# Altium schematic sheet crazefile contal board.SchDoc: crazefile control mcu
size A4; CompanyName: 良工作室; DrawnBy: 郑良杰; Engineer: 郑良杰; Organization: 良工作室; DocumentNumber: 1; SheetNumber: 1; SheetTotal: 4
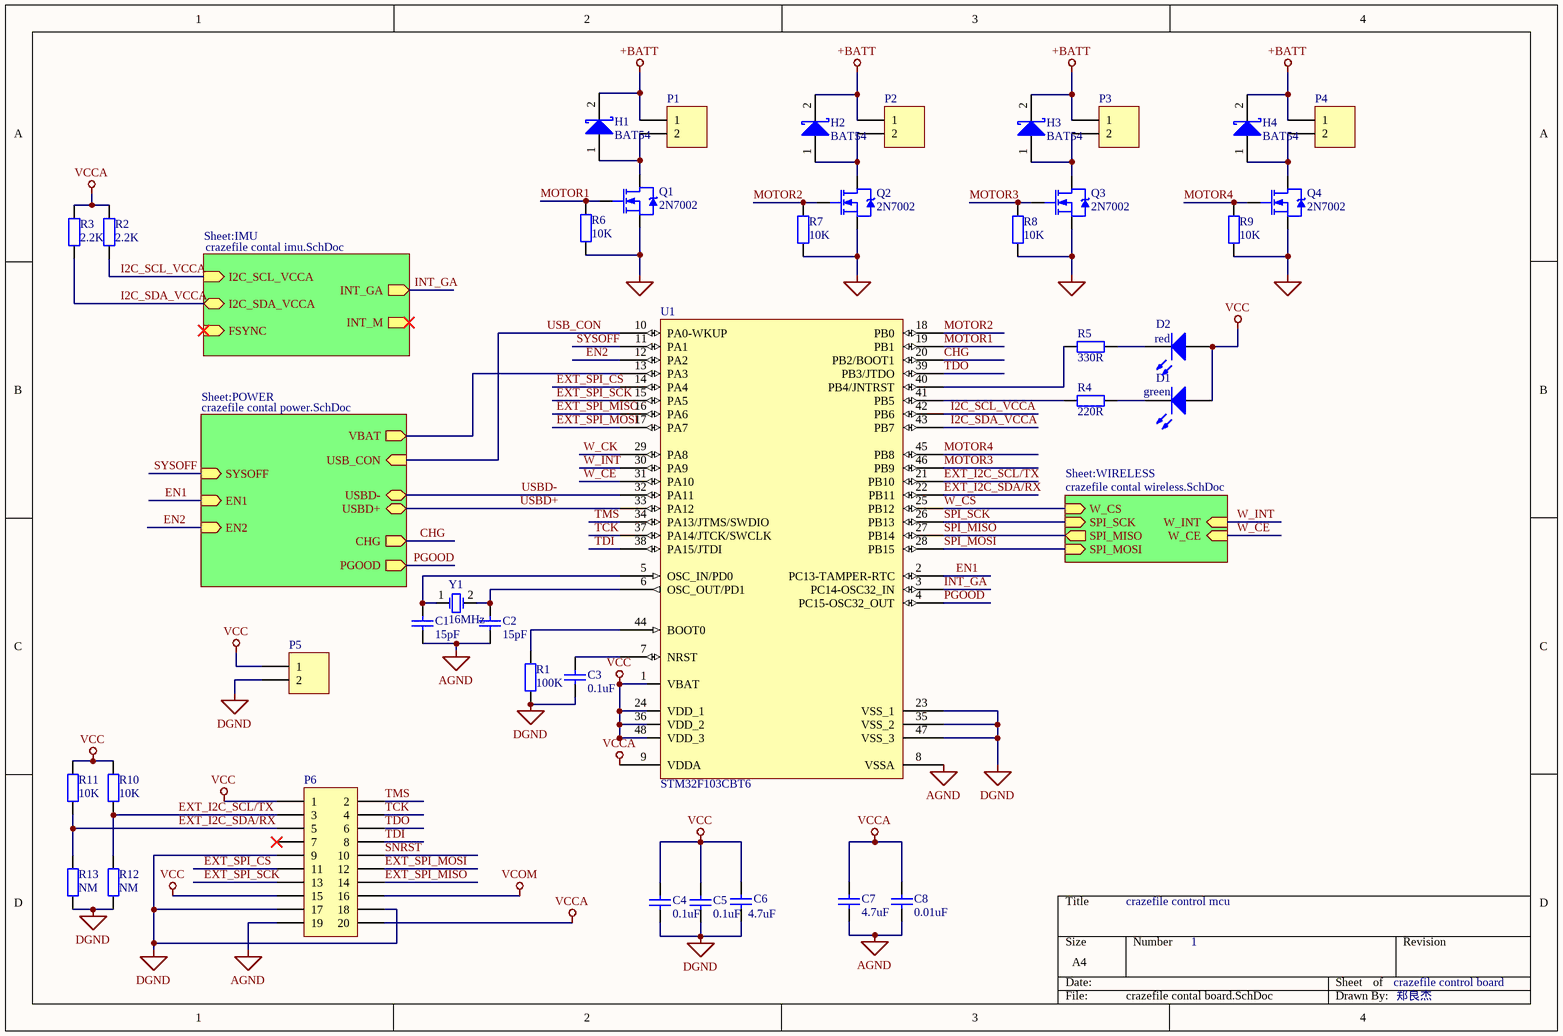
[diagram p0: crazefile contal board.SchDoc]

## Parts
C1  value 15pF  [CAP_0603]  (hidden comment: Cap)
C2  value 15pF  [CAP_0603]  (hidden comment: Cap)
C3  value 0.1uF  [CAP_0603]  (hidden comment: Cap)
C4  value 0.1uF  [CAP_0603]  (hidden comment: Cap)
C5  value 0.1uF  [CAP_0603]  (hidden comment: Cap)
C6  value 4.7uF  [CAP_0603]  (hidden comment: Cap)
C7  value 4.7uF  [CAP_0603]  (hidden comment: Cap)
C8  value 0.01uF  [CAP_0603]  (hidden comment: Cap)
D1  LED0  [LED_0603_GREEN]  (value not drawn)
D2  LED0  [LED_0603_RED]  (value not drawn)
H1  BAT54  [SOD-523]
H2  BAT54  [SOD-523]
H3  BAT54  [SOD-523]
H4  BAT54  [SOD-523]
P1  Header 2  [HDR1X2_180_2.54]  (value not drawn)
P2  Header 2  [HDR1X2_180_2.54]  (value not drawn)
P3  Header 2  [HDR1X2_180_2.54]  (value not drawn)
P4  Header 2  [HDR1X2_180_2.54]  (value not drawn)
P5  Header 2  [HDR1X2_180_2.54]  (value not drawn)
P6  Header 10X2  [HDR2X10]  (value not drawn)
Q1  2N7002  [SI2302]
Q2  2N7002  [SI2302]
Q3  2N7002  [SI2302]
Q4  2N7002  [SI2302]
R1  value 100K  [RES_0603]  (hidden comment: Res2)
R2  value 2.2K  [RES_0603]  (hidden comment: Res2)
R3  value 2.2K  [RES_0603]  (hidden comment: Res2)
R4  value 220R  [RES_0603]  (hidden comment: Res2)
R5  value 330R  [RES_0603]  (hidden comment: Res2)
R6  value 10K  [RES_0603]  (hidden comment: Res2)
R7  value 10K  [RES_0603]  (hidden comment: Res2)
R8  value 10K  [RES_0603]  (hidden comment: Res2)
R9  value 10K  [RES_0603]  (hidden comment: Res2)
R10  value 10K  [RES_0603]  (hidden comment: Res2)
R11  value 10K  [RES_0603]  (hidden comment: Res2)
R12  value NM  [RES_0603]  (hidden comment: Res2)
R13  value NM  [RES_0603]  (hidden comment: Res2)
U1  STM32F103CBT6  [LQFP48_N]
Y1  value 16MHz  [XTAL_5032]  (hidden comment: XTAL_5032)

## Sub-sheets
Sheet:IMU = crazefile contal imu.SchDoc: I2C_SCL_VCCA (in), I2C_SDA_VCCA, INT_GA (out), INT_M (out), FSYNC (in)
Sheet:POWER = crazefile contal power.SchDoc: SYSOFF (in), EN1 (in), EN2 (in), USBD-, USBD+, USB_CON (in), VBAT (out), CHG (out), PGOOD (out)
Sheet:WIRELESS = crazefile contal wireless.SchDoc: W_CS (in), SPI_SCK (in), SPI_MISO (out), SPI_MOSI (in), W_INT (in), W_CE (in)

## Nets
+BATT: H1.2 H2.2 H3.2 H4.2 P1.1 P2.1 P3.1 P4.1
AGND: C1.1 C2.1 C7.1 C8.2 P6.19 U1.8(VSSA)
DGND: C3.2 C4.1 C5.2 C6.1 P5.2 P6.9 P6.17 P6.18 R1.1 R12.1 R13.2 U1.23(VSS_1) U1.35(VSS_2) U1.47(VSS_3)
GND: Q1.2(S) Q2.2(S) Q3.2(S) Q4.2(S) R6.1 R7.1 R8.1 R9.1
VCC: C4.2 C5.1 C6.2 D1.1(A) D2.1(A) P5.1 P6.1 P6.15 R10.1 R11.1 U1.1(VBAT) U1.24(VDD_1) U1.36(VDD_2) U1.48(VDD_3)
VCCA: C7.2 C8.1 P6.20 R2.2 R3.2 U1.9(VDDA)
VCOM: P6.16
CHG: U1.20(PB2/BOOT1) ; sheet Sheet:POWER/CHG
EN1: U1.2(PC13-TAMPER-RTC) ; sheet Sheet:POWER/EN1
EN2: U1.12(PA2) ; sheet Sheet:POWER/EN2
EXT_I2C_SCL/TX: P6.3 R10.2 R12.2 U1.21(PB10)
EXT_I2C_SDA/RX: P6.5 R11.2 R13.1 U1.22(PB11)
EXT_SPI_CS: P6.11 U1.14(PA4)
EXT_SPI_MISO: P6.14 U1.16(PA6)
EXT_SPI_MOSI: P6.12 U1.17(PA7)
EXT_SPI_SCK: P6.13 U1.15(PA5)
I2C_SCL_VCCA: R2.1 U1.42(PB6) ; sheet Sheet:IMU/I2C_SCL_VCCA
I2C_SDA_VCCA: R3.1 U1.43(PB7) ; sheet Sheet:IMU/I2C_SDA_VCCA
INT_GA: U1.3(PC14-OSC32_IN) ; sheet Sheet:IMU/INT_GA
MOTOR1: Q1.1(G) R6.2 U1.19(PB1)
MOTOR2: Q2.1(G) R7.2 U1.18(PB0)
MOTOR3: Q3.1(G) R8.2 U1.46(PB9)
MOTOR4: Q4.1(G) R9.2 U1.45(PB8)
PGOOD: U1.4(PC15-OSC32_OUT) ; sheet Sheet:POWER/PGOOD
SNRST: P6.10
SPI_MISO: U1.27(PB14) ; sheet Sheet:WIRELESS/SPI_MISO
SPI_MOSI: U1.28(PB15) ; sheet Sheet:WIRELESS/SPI_MOSI
SPI_SCK: U1.26(PB13) ; sheet Sheet:WIRELESS/SPI_SCK
SYSOFF: U1.11(PA1) ; sheet Sheet:POWER/SYSOFF
TCK: P6.4 U1.37(PA14/JTCK/SWCLK)
TDI: P6.8 U1.38(PA15/JTDI)
TDO: P6.6 U1.39(PB3/JTDO)
TMS: P6.2 U1.34(PA13/JTMS/SWDIO)
USB_CON: U1.10(PA0-WKUP) ; sheet Sheet:POWER/USB_CON
USBD+: U1.33(PA12) ; sheet Sheet:POWER/USBD+
USBD-: U1.32(PA11) ; sheet Sheet:POWER/USBD-
W_CE: U1.31(PA10) ; sheet Sheet:WIRELESS/W_CE
W_CK: U1.29(PA8)
W_CS: U1.25(PB12) ; sheet Sheet:WIRELESS/W_CS
W_INT: U1.30(PA9) ; sheet Sheet:WIRELESS/W_INT
NetC1_2: C1.2 U1.5(OSC_IN/PD0) Y1.1(OSC1)
NetC2_2: C2.2 U1.6(OSC_OUT/PD1) Y1.2(OSC2)
NetC3_1: C3.1 U1.7(NRST)
NetD1_2: D1.2(K) R4.2
NetD2_2: D2.2(K) R5.2
NetH1_1: H1.1 P1.2 Q1.3(D)
NetH2_1: H2.1 P2.2 Q2.3(D)
NetH3_1: H3.1 P3.2 Q3.3(D)
NetH4_1: H4.1 P4.2 Q4.3(D)
NetR1_2: R1.2 U1.44(BOOT0)
NetR4_1: R4.1 U1.41(PB5)
NetR5_1: R5.1 U1.40(PB4/JNTRST)
NetU1_13: U1.13(PA3) ; sheet Sheet:POWER/VBAT

Not connected (* = marked no-connect by the designer): P6 7*

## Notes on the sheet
- (near D2) red
- (near D1) green

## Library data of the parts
C1-C8 = Cap: Capacitor
D1 D2 = LED0: Typical INFRARED GaAs LED
H1-H4 = BAT54: Schottky Diode
P1-P5 = Header 2: Header, 2-Pin
P6 = Header 10X2: Header, 10-Pin, Dual row
Q1-Q4 = SI2302_1
R1-R13 = Res2: Resistor
U1 = STM32F103CBT6: STM32 ARM-based 32-bit MCU with 128 Kbytes Flash, 48-pin LQFP, Industrial Temperature
Y1 = XTAL_5032: Crystal Oscillator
